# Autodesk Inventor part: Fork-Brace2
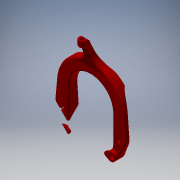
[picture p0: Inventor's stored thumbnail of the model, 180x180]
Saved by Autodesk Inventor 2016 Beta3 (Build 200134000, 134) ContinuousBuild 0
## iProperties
Shininess: 64.0
Length Units: 11272
Angle Units: 11279
Time Units: 11290
Mass Units: 11286
Length Display Precision: 3
Angle Display Precision: 2
Compacted: True
Part Number: Fork-Brace2
Document SubType Name: Modeling
Created: 2003-10
Designer: Autodesk, Inc.
Manufacturer: Standard
Standards Organization: Custom
Mass: 76.099 g
Surface Area: 223.863 cm^2
Volume: 76.099 cm^3
Density: 1 g/cm^3
Material: Generic
Appearance: Red (Flat)_1
Density: 0.0
Volumn: 0.0
Area: 0.0
PropertySet Name: Model Information
Control State: 0
Master: False
Checked Out: False
Translation Standard: STEP AP214DIS
Preprocessor: Autodesk Inventor 8 Pre-Release
Postprocessor: Build: 057b, Release: 8 Pre-Release - Date: Sun 09/16/2003
Sent Units: INCHES
Uncertainty: 1.0000000000000002e-06
Author: Autodesk, Inc.
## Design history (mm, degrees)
feature "Base1"
sketch "Sketch1"
  geometry: L1 (-40.83, 0)-(-40.83, -45.941); L2 (38.288, -53.783)-(39.968, -52.909) reference; L3 (55.902, -40.649)-(48.019, -56.676) reference; L4 (54.945, 5.098)-(58.089, -28.786) reference; L5 (-27.85, 47.638)-(27.85, 47.638) reference; L6 (-58.09, -28.785)-(-54.945, 5.1) reference; L7 (-48.02, -56.678)-(-55.904, -40.648) reference; L8 (-39.968, -52.909)-(-38.288, -53.783) reference; L9 (-40.83, 0)-(-40.83, -45.941) reference; L10 (40.831, -45.941)-(40.831, 0) reference; C1 r 6.35 at (-48.578, -36.14); A1 r 7.302 centre (41.657, -60.261) between (48.019, -56.676) and (38.288, -53.783) reference; A2 r 22.225 centre (35.959, -30.839) between (55.902, -40.649) and (58.184, -30.839) reference; A3 r 22.225 centre (35.959, -30.839) between (58.184, -30.839) and (58.089, -28.786) reference; A4 r 55.181 centre (0, 0) between (54.945, 5.098) and (27.85, 47.638) reference; A5 r 55.182 centre (0, 0) between (-27.85, 47.638) and (-54.945, 5.1) reference; A6 r 22.225 centre (-35.961, -30.839) between (-58.09, -28.785) and (-58.186, -30.839) reference; A7 r 22.225 centre (-35.961, -30.839) between (-58.186, -30.839) and (-55.904, -40.648) reference; A8 r 7.302 centre (-41.657, -60.261) between (-38.288, -53.783) and (-48.02, -56.678) reference; A9 r 28.575 centre (-12.255, -45.941) between (-40.83, -45.941) and (-39.968, -52.909) reference; A10 r 40.83 centre (0, 0) between (40.831, 0) and (-40.83, 0) reference; A11 r 28.575 centre (12.255, -45.941) between (39.968, -52.909) and (40.831, -45.941) reference
  constraints: 2 end point, 1 centre point
  dimensions: "d15" = 7.74707 distance from line of C1.centre L1
hole "Hole1" sketch "Sketch1" at (-48.578, -36.14) diameter "d0" = 3.2512; stored, may be unused: countersink angle "d4" = 90 deg, drill point angle "d6" = 118 deg; dims "d1" = 12.7, "d2" = 7.62, "d3" = 6.35, "d5" = 19.05
workplane "Work Plane1"
sketch "Sketch2"
  geometry: C1 r 3.81 at (-89.044, -0.261) reference
hole "Hole2" sketch "Sketch2" at (-89.044, -0.261) diameter "d7" = 12.7; stored, may be unused: countersink angle "d11" = 0.1 deg, drill point angle "d13" = 0 deg; dims "d8" = 12.7, "d9" = 9.525, "d10" = 6.35, "d12" = 12.7
workaxis "Work Axis1"
workplane "Work Plane2"
mirror "Mirror1"
body "Solid1"
other parameters: "d14" = 0
